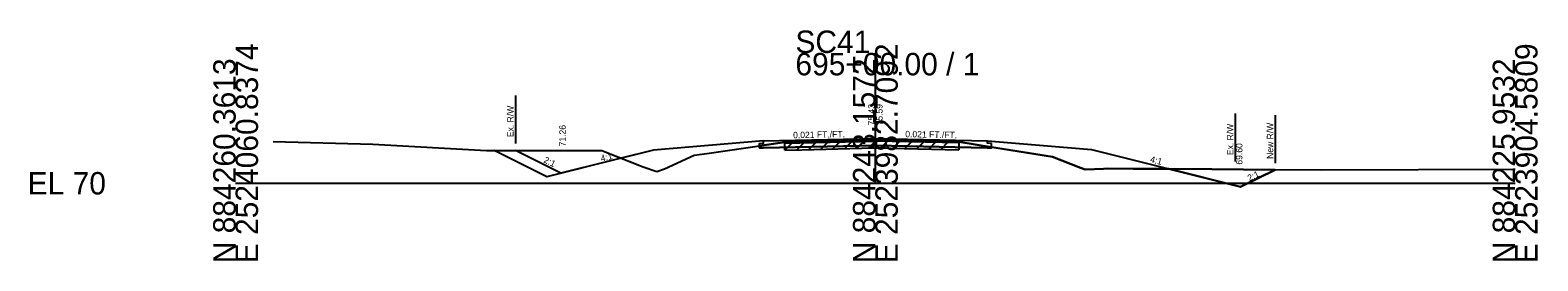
# Model space of a CAD drawing. Extents: x -26 to 183, y -10 to 24021.
# Drawn here: x -25.7 to 162.8, y 19490.3 to 19519.1 of the extents above; entities that cross this region are included whole.
import ezdxf

# ---------------------------------------------------------------- set-up
doc = ezdxf.new("R2010")
doc.units = 0
for name, color, linetype in [('RD_GPK_XS_Cell', 7, 'Continuous'), ('RD_XS_Base', 7, 'Continuous'), ('RD_XS_Buildup', 7, 'Continuous'), ('RD_XS_EarthShd', 7, 'Continuous'), ('RD_XS_EwShp', 7, 'Continuous'), ('RD_XS_ExGround', 7, 'Continuous'), ('RD_XS_ExPaveRet', 7, 'Continuous'), ('RD_XS_ExRW', 7, 'Continuous'), ('RD_XS_NewRW', 7, 'Continuous'), ('RD_XS_Pave', 7, 'Continuous'), ('RD_XS_TieSlope', 7, 'Continuous'), ('RD_XS_TX_Elev_EX', 7, 'Continuous'), ('RD_XS_TX_Elev_PR', 7, 'Continuous'), ('RD_XS_TX_Slope', 7, 'Continuous')]:
    doc.layers.add(name, color=color, linetype=linetype)

msp = doc.modelspace()

# ---------------------------------------------------------------- linework, layer by layer
at = {"layer": 'RD_GPK_XS_Cell'}
for p, q in [((80, 19500), (80, 19516.29)), ((0, 19500), (80, 19500)), ((80, 19500), (160, 19500))]:
    msp.add_line(p, q, dxfattribs=at)
at = {"layer": 'RD_XS_Base'}
for p in [(66.01, 19504.45), (93.98, 19504.45)]:
    msp.add_line(p, (80, 19504.74), dxfattribs=at)
at = {"layer": 'RD_XS_Buildup'}
for p, q in [((68.66, 19505.03), (80, 19505.27)), ((68.66, 19504.93), (68.66, 19505.03)), ((90.44, 19505.05), (80, 19505.27)), ((90.44, 19504.98), (90.44, 19505.05))]:
    msp.add_line(p, q, dxfattribs=at)
at = {"layer": 'RD_XS_EarthShd'}
for p, q in [((66, 19505.29), (52.25, 19504.15)), ((94, 19505.29), (107.04, 19504.21))]:
    msp.add_line(p, q, dxfattribs=at)
at = {"layer": 'RD_XS_EwShp'}
for points in [[(32.35, 19504.1), (41.29, 19504.09), (45.79, 19504.08), (48.22, 19503.14), (38.92, 19500.82)], [(48.22, 19503.14), (38.92, 19500.82), (32.35, 19504.1), (41.29, 19504.09), (45.79, 19504.08)], [(48.22, 19503.14), (38.92, 19500.82), (32.35, 19504.1), (41.29, 19504.09), (45.79, 19504.08)], [(50.98, 19502.07), (52.68, 19501.48), (53.61, 19501.82), (57.34, 19503.53), (59.2, 19503.78), (65.5, 19504.68), (65.5, 19504.99), (66, 19505), (66, 19505.29), (52.25, 19504.15), (48.22, 19503.14)], [(52.68, 19501.48), (53.61, 19501.82), (57.34, 19503.53), (59.2, 19503.78), (65.5, 19504.68), (65.5, 19504.99), (66, 19505), (66, 19505.29), (52.25, 19504.15), (48.22, 19503.14), (50.98, 19502.07)], [(52.68, 19501.48), (53.61, 19501.82), (57.34, 19503.53), (59.2, 19503.78), (65.5, 19504.68), (65.5, 19504.99), (66, 19505), (66, 19505.29), (52.25, 19504.15), (48.22, 19503.14), (50.98, 19502.07)], [(65.5, 19504.44), (66.01, 19504.45), (80, 19504.74), (93.98, 19504.45), (94.5, 19504.44), (94.5, 19504.53), (90.44, 19505.18), (81.91, 19505.38), (79.8, 19505.43), (70.81, 19505.18), (68.67, 19505.13), (65.5, 19504.68)], [(90.44, 19505.18), (94.5, 19504.53), (94.5, 19504.44), (93.98, 19504.45), (80, 19504.74), (66.01, 19504.45), (65.5, 19504.44), (65.5, 19504.68), (68.67, 19505.13), (70.81, 19505.18), (79.8, 19505.43), (81.91, 19505.38)], [(90.44, 19505.18), (94.5, 19504.53), (94.5, 19504.44), (93.98, 19504.45), (80, 19504.74), (66.01, 19504.45), (65.5, 19504.44), (65.5, 19504.68), (68.67, 19505.13), (70.81, 19505.18), (79.8, 19505.43), (81.91, 19505.38)], [(94.5, 19504.99), (94, 19505), (94, 19505.29), (107.04, 19504.21), (116.71, 19501.79), (112.25, 19501.82), (109.03, 19501.84), (108.53, 19501.79), (106.25, 19501.72), (105.63, 19501.95), (102.15, 19503.31), (100.07, 19503.64), (94.5, 19504.53)], [(94.5, 19504.99), (94, 19505), (94, 19505.29), (107.04, 19504.21), (116.71, 19501.79), (112.25, 19501.82), (109.03, 19501.84), (108.53, 19501.79), (106.25, 19501.72), (105.63, 19501.95), (102.15, 19503.31), (100.07, 19503.64), (94.5, 19504.53)], [(94.5, 19504.99), (94, 19505), (94, 19505.29), (107.04, 19504.21), (116.71, 19501.79), (112.25, 19501.82), (109.03, 19501.84), (108.53, 19501.79), (106.25, 19501.72), (105.63, 19501.95), (102.15, 19503.31), (100.07, 19503.64), (94.5, 19504.53)], [(116.71, 19501.79), (125.67, 19499.55), (129.98, 19501.7), (122.08, 19501.75)], [(122.08, 19501.75), (129.98, 19501.7), (125.67, 19499.55), (116.71, 19501.79)], [(122.08, 19501.75), (129.98, 19501.7), (125.67, 19499.55), (116.71, 19501.79)]]:
    msp.add_lwpolyline(points, close=True, dxfattribs=at)
at = {"layer": 'RD_XS_ExGround'}
for p, q in [((4.7, 19505.23), (17.17, 19504.89)), ((17.17, 19504.89), (31.36, 19504.1)), ((31.36, 19504.1), (41.29, 19504.09)), ((41.29, 19504.09), (45.79, 19504.08)), ((45.79, 19504.08), (50.98, 19502.07)), ((57.34, 19503.53), (59.2, 19503.78)), ((59.2, 19503.78), (68.67, 19505.13)), ((68.67, 19505.13), (70.81, 19505.18)), ((70.81, 19505.18), (79.8, 19505.43)), ((79.8, 19505.43), (81.91, 19505.38)), ((81.91, 19505.38), (90.44, 19505.18)), ((90.44, 19505.18), (100.07, 19503.64)), ((50.98, 19502.07), (52.68, 19501.48)), ((52.68, 19501.48), (53.61, 19501.82)), ((53.61, 19501.82), (57.34, 19503.53)), ((100.07, 19503.64), (102.15, 19503.31)), ((102.15, 19503.31), (105.63, 19501.95)), ((105.63, 19501.95), (106.25, 19501.72)), ((108.53, 19501.79), (109.03, 19501.84)), ((109.03, 19501.84), (112.25, 19501.82)), ((112.25, 19501.82), (122.08, 19501.75)), ((106.25, 19501.72), (108.53, 19501.79)), ((122.08, 19501.75), (135.8, 19501.67)), ((135.8, 19501.67), (160, 19501.75))]:
    msp.add_line(p, q, dxfattribs=at)
at = {"layer": 'RD_XS_ExPaveRet'}
for p, q in [((68.67, 19504.13), (69.69, 19505.15)), ((68.67, 19504.13), (68.67, 19505.13)), ((68.67, 19504.13), (70.81, 19504.18)), ((70.17, 19504.17), (71.19, 19505.19)), ((70.81, 19504.18), (79.8, 19504.43)), ((71.67, 19504.21), (72.69, 19505.24)), ((73.17, 19504.25), (74.19, 19505.28)), ((74.67, 19504.29), (75.69, 19505.32)), ((76.17, 19504.33), (77.19, 19505.36)), ((77.67, 19504.37), (78.69, 19505.4)), ((79.17, 19504.41), (80.17, 19505.42)), ((79.8, 19504.43), (81.91, 19504.38)), ((80.67, 19504.41), (81.64, 19505.39)), ((81.91, 19504.38), (90.44, 19504.18)), ((82.17, 19504.38), (83.14, 19505.35)), ((83.67, 19504.34), (84.64, 19505.32)), ((85.17, 19504.3), (86.14, 19505.28)), ((86.67, 19504.27), (87.64, 19505.25)), ((88.17, 19504.23), (89.14, 19505.21)), ((90.44, 19505.18), (90.44, 19504.18))]:
    msp.add_line(p, q, dxfattribs=at)
at = {"layer": 'RD_XS_ExRW'}
for p, q in [((35, 19510.98), (35, 19504.98)), ((125, 19508.73), (125, 19502.73))]:
    msp.add_line(p, q, dxfattribs=at)
at = {"layer": 'RD_XS_NewRW'}
msp.add_line((130, 19508.5), (130, 19502.5), dxfattribs=at)
at = {"layer": 'RD_XS_Pave'}
for p, q in [((66, 19505.29), (80, 19505.59)), ((80, 19505.59), (94, 19505.29)), ((65.5, 19504.99), (66, 19505)), ((65.5, 19504.44), (65.5, 19504.99)), ((65.5, 19504.44), (66.01, 19504.45)), ((66, 19505), (66, 19505.29)), ((94.5, 19504.44), (93.98, 19504.45)), ((94, 19505), (94, 19505.29)), ((94.5, 19504.99), (94, 19505)), ((94.5, 19504.44), (94.5, 19504.99))]:
    msp.add_line(p, q, dxfattribs=at)
at = {"layer": 'RD_XS_TieSlope'}
for p, q in [((40.68, 19501.26), (35, 19504.1)), ((52.25, 19504.15), (40.68, 19501.26)), ((107.04, 19504.21), (125.67, 19499.55)), ((125.67, 19499.55), (129.98, 19501.7))]:
    msp.add_line(p, q, dxfattribs=at)

# ---------------------------------------------------------------- texts
at = {"layer": 'RD_GPK_XS_Cell'}
for s, p in [('SC41', (70, 19516.29)), ('695+00.00 / 1', (70, 19513.49)), ('EL 70', (-26, 19498.6))]:
    msp.add_text(s, height=2.8, dxfattribs=at).set_placement(p)
for s, p in [('E 2524060.8374', (2.8, 19490)), ('E 2523982.7092', (82.8, 19490)), ('E 2523904.5809', (162.8, 19490)), ('N 884260.3613', (0, 19490)), ('N 884243.1572', (80, 19490)), ('N 884225.9532', (160, 19490))]:
    msp.add_text(s, height=2.8, rotation=90, dxfattribs=at).set_placement(p)
at = {"layer": 'RD_XS_ExRW'}
for p in [(34.75, 19505.77), (124.75, 19503.52)]:
    msp.add_text('Ex. R/W ', height=0.8, rotation=90, dxfattribs=at).set_placement(p)
at = {"layer": 'RD_XS_NewRW'}
msp.add_text('New R/W ', height=0.8, rotation=90, dxfattribs=at).set_placement((129.75, 19503.05))
at = {"layer": 'RD_XS_TX_Elev_EX'}
msp.add_text('75.43', height=0.8, rotation=90, dxfattribs=at).set_placement((79.9, 19507.23))
at = {"layer": 'RD_XS_TX_Elev_PR'}
for s, p in [('75.59', (80.9, 19507.23)), ('71.26', (41.27, 19504.61)), ('69.60', (125.9, 19502.33))]:
    msp.add_text(s, height=0.8, rotation=90, dxfattribs=at).set_placement(p)
at = {"layer": 'RD_XS_TX_Slope'}
for s, rotation, p in [('0.021 FT./FT.', 1.1916, (69.72, 19505.62)), ('0.021 FT./FT.', 358.8084, (83.73, 19505.76)), ('4:1', 14.0362, (45.75, 19502.69)), ('2:1', 333.4349, (38.44, 19502.66)), ('4:1', 345.9638, (114.3, 19502.65)), ('2:1', 26.5651, (126.77, 19500.23))]:
    msp.add_text(s, height=0.8, rotation=rotation, dxfattribs=at).set_placement(p)

doc.saveas('drawing.dxf')
